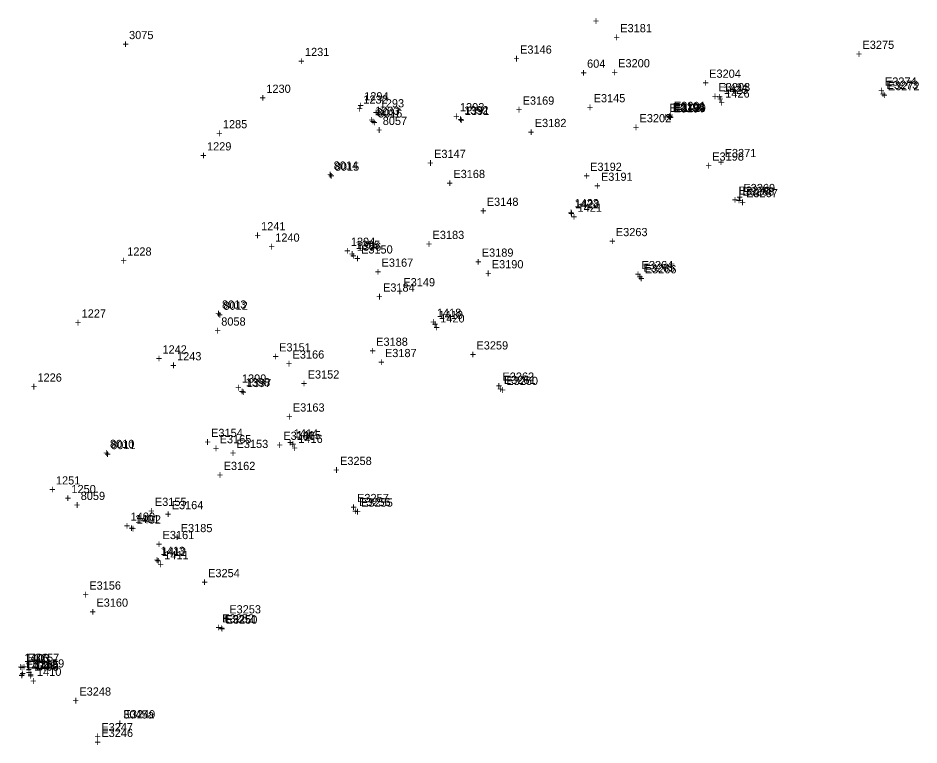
# Model space of a CAD drawing. Extents: x 1667192 to 1669644, y 336680 to 339991.
# Drawn here: x 1668014.4 to 1668289.1, y 339181.7 to 339403.5 of the extents above; entities that cross this region are included whole.
import ezdxf

# ---------------------------------------------------------------- set-up
doc = ezdxf.new("R2010")
doc.units = 0
for name, color, linetype in [('S_Control_Temp_Traverse', 7, 'Continuous'), ('S_Curb_Type_1', 7, 'Continuous'), ('S_Curb_Type_5', 7, 'Continuous'), ('S_Drainage_CB', 7, 'Continuous'), ('S_Drainage_Culvert_Top', 7, 'Continuous'), ('S_Drainage_Invert', 7, 'Continuous'), ('S_Drainage_Sump', 7, 'Continuous'), ('S_Fencing_Page', 7, 'Continuous'), ('S_Ground_Elevation', 7, 'Continuous'), ('S_Roadway_Edge_Pavement', 7, 'Continuous'), ('S_Roadway_Edge_TW', 7, 'Continuous'), ('S_Traffic_Sign_SinglePost', 7, 'Continuous'), ('S_Trees_TreeLine', 7, 'Continuous')]:
    doc.layers.add(name, color=color, linetype=linetype)

msp = doc.modelspace()

# ---------------------------------------------------------------- texts
at = {"layer": 'S_Control_Temp_Traverse'}
for s, p in [('604', (1668187.89, 339388.33)), ('604', (1668187.89, 339388.33)), ('604', (1668187.89, 339388.33)), ('604', (1668187.89, 339388.33)), ('604', (1668187.89, 339388.33)), ('604', (1668187.89, 339388.33)), ('604', (1668187.89, 339388.33)), ('604', (1668187.89, 339388.33)), ('604', (1668187.89, 339388.33)), ('+', (1668185.83, 339385.58)), ('+', (1668185.83, 339385.58)), ('+', (1668185.83, 339385.58)), ('+', (1668185.83, 339385.58)), ('+', (1668185.83, 339385.58)), ('+', (1668185.83, 339385.58)), ('+', (1668185.83, 339385.58)), ('+', (1668185.83, 339385.58)), ('+', (1668185.83, 339385.58))]:
    msp.add_text(s, height=2.5, dxfattribs=at).set_placement(p)
at = {"layer": 'S_Curb_Type_1'}
for s, p in [('1424', (1668229.43, 339381)), ('+', (1668227.37, 339378.25)), ('8017', (1668123.69, 339373.48)), ('1391', (1668150.63, 339373.9)), ('+', (1668121.63, 339370.73)), ('+', (1668148.57, 339371.15)), ('8014', (1668110.63, 339357.25)), ('+', (1668108.57, 339354.5)), ('1423', (1668184.06, 339345.77)), ('+', (1668182, 339343.02)), ('1396', (1668117.69, 339332.5)), ('+', (1668115.62, 339329.75)), ('8013', (1668076.56, 339314.85)), ('1418', (1668142.09, 339312.32)), ('+', (1668074.5, 339312.1)), ('+', (1668140.03, 339309.57)), ('1397', (1668084.14, 339290.91)), ('+', (1668082.08, 339288.16)), ('1414', (1668098.44, 339275.52)), ('8010', (1668042.4, 339272.32)), ('+', (1668096.38, 339272.77)), ('+', (1668040.34, 339269.57)), ('1402', (1668050.53, 339249.25)), ('+', (1668048.47, 339246.5)), ('1413', (1668057.84, 339239.68)), ('+', (1668055.77, 339236.93)), ('1404', (1668016.67, 339204.62)), ('1403', (1668016.68, 339206.91)), ('1405', (1668019.34, 339204.8)), ('+', (1668014.62, 339204.16)), ('+', (1668014.61, 339201.87)), ('+', (1668017.28, 339202.05))]:
    msp.add_text(s, height=2.5, dxfattribs=at).set_placement(p)
at = {"layer": 'S_Curb_Type_5'}
for s, p in [('E3272', (1668279.6, 339381.48)), ('+', (1668277.54, 339378.73)), ('E3267', (1668236.38, 339348.83)), ('+', (1668234.32, 339346.08)), ('E3266', (1668205.47, 339325.6)), ('+', (1668203.41, 339322.85)), ('E3260', (1668163.25, 339291.55)), ('+', (1668161.19, 339288.8)), ('E3255', (1668118.98, 339254.42)), ('+', (1668116.92, 339251.67)), ('E3250', (1668077.67, 339218.71)), ('+', (1668075.61, 339215.96)), ('3045a', (1668046.47, 339189.81)), ('E3249', (1668046.52, 339189.85)), ('+', (1668044.41, 339187.06)), ('+', (1668044.46, 339187.1))]:
    msp.add_text(s, height=2.5, dxfattribs=at).set_placement(p)
at = {"layer": 'S_Drainage_CB'}
for s, p in [('E3201', (1668214.36, 339375.43)), ('+', (1668212.3, 339372.68)), ('E3270', (1668234.09, 339349.59)), ('+', (1668232.03, 339346.84)), ('E3253', (1668078.78, 339221.86)), ('+', (1668076.72, 339219.11))]:
    msp.add_text(s, height=2.5, dxfattribs=at).set_placement(p)
at = {"layer": 'S_Drainage_Culvert_Top'}
for s, p in [('E3200', (1668197.37, 339388.45)), ('+', (1668195.31, 339385.7)), ('E3197', (1668214.21, 339374.68)), ('E3199', (1668214.43, 339374.79)), ('+', (1668212.15, 339371.93)), ('+', (1668212.36, 339372.04)), ('E3198', (1668226.05, 339359.99)), ('+', (1668223.99, 339357.24))]:
    msp.add_text(s, height=2.5, dxfattribs=at).set_placement(p)
at = {"layer": 'S_Drainage_Invert'}
for s, p in [('E3195', (1668214.17, 339375.02)), ('+', (1668212.11, 339372.27))]:
    msp.add_text(s, height=2.5, dxfattribs=at).set_placement(p)
at = {"layer": 'S_Drainage_Sump'}
for s, p in [('E3194', (1668214.05, 339375.08)), ('+', (1668211.99, 339372.33))]:
    msp.add_text(s, height=2.5, dxfattribs=at).set_placement(p)
at = {"layer": 'S_Fencing_Page'}
for s, p in [('3075', (1668048.22, 339397.06)), ('+', (1668046.16, 339394.31))]:
    msp.add_text(s, height=2.5, dxfattribs=at).set_placement(p)
at = {"layer": 'S_Ground_Elevation'}
for s, p in [('+', (1668189.66, 339401.4)), ('E3181', (1668198, 339399.15)), ('+', (1668195.94, 339396.4)), ('1231', (1668101.86, 339391.9)), ('E3146', (1668167.45, 339392.62)), ('+', (1668099.8, 339389.15)), ('+', (1668165.39, 339389.87)), ('E3204', (1668225.12, 339385.27)), ('1230', (1668090.08, 339380.67)), ('+', (1668223.06, 339382.52)), ('E3203', (1668227.95, 339381.17)), ('1294', (1668119.91, 339378.37)), ('E3145', (1668189.89, 339377.79)), ('+', (1668225.89, 339378.42)), ('+', (1668088.02, 339377.92)), ('+', (1668117.85, 339375.62)), ('1232', (1668119.64, 339377.37)), ('1293', (1668124.65, 339376.23)), ('E3169', (1668168.23, 339377.06)), ('+', (1668117.58, 339374.62)), ('+', (1668122.58, 339373.48)), ('1233', (1668123.26, 339373.94)), ('+', (1668166.17, 339374.31)), ('+', (1668187.83, 339375.04)), ('E3193', (1668212.97, 339374.84)), ('+', (1668121.2, 339371.19)), ('E3182', (1668171.92, 339370.23)), ('+', (1668210.91, 339372.09)), ('+', (1668169.86, 339367.48)), ('1229', (1668071.99, 339363.1)), ('+', (1668069.93, 339360.35)), ('E3147', (1668141.22, 339360.79)), ('+', (1668139.16, 339358.04)), ('E3192', (1668188.82, 339356.87)), ('E3168', (1668147.11, 339354.67)), ('+', (1668186.76, 339354.12)), ('E3191', (1668192.12, 339353.84)), ('+', (1668145.05, 339351.92)), ('+', (1668190.06, 339351.09)), ('E3148', (1668157.3, 339346.2)), ('+', (1668155.24, 339343.45)), ('1241', (1668088.48, 339338.73)), ('+', (1668086.42, 339335.98)), ('1240', (1668092.79, 339335.27)), ('E3183', (1668140.76, 339336.08)), ('1228', (1668047.65, 339331.02)), ('+', (1668090.73, 339332.52)), ('E3150', (1668118.95, 339331.65)), ('+', (1668138.7, 339333.33)), ('+', (1668116.89, 339328.9)), ('E3189', (1668155.77, 339330.68)), ('+', (1668045.58, 339328.27)), ('E3167', (1668125.21, 339327.62)), ('+', (1668153.71, 339327.93)), ('E3190', (1668158.82, 339327.13)), ('+', (1668123.15, 339324.87)), ('+', (1668156.76, 339324.38)), ('E3184', (1668125.66, 339320.02)), ('E3149', (1668131.86, 339321.65)), ('+', (1668129.8, 339318.9)), ('+', (1668123.6, 339317.27)), ('1227', (1668033.76, 339312.12)), ('+', (1668031.7, 339309.37)), ('1242', (1668058.4, 339301.15)), ('E3151', (1668093.98, 339301.78)), ('E3188', (1668123.57, 339303.5)), ('1243', (1668062.84, 339299.06)), ('+', (1668091.92, 339299.03)), ('E3166', (1668098.07, 339299.6)), ('+', (1668121.51, 339300.75)), ('E3187', (1668126.25, 339300.05)), ('+', (1668056.34, 339298.4)), ('+', (1668060.78, 339296.31)), ('+', (1668096.01, 339296.85)), ('+', (1668124.19, 339297.3)), ('1226', (1668020.28, 339292.57)), ('E3152', (1668102.67, 339293.52)), ('+', (1668100.61, 339290.77)), ('+', (1668018.22, 339289.82)), ('E3163', (1668098.17, 339283.44)), ('+', (1668096.11, 339280.69)), ('E3154', (1668073.24, 339275.68)), ('E3165', (1668075.84, 339273.77)), ('E3186', (1668095.25, 339274.79)), ('+', (1668071.18, 339272.93)), ('+', (1668073.78, 339271.02)), ('E3153', (1668080.99, 339272.32)), ('+', (1668093.19, 339272.04)), ('+', (1668078.93, 339269.57)), ('E3162', (1668077.06, 339265.61)), ('+', (1668075, 339262.86)), ('1251', (1668025.92, 339261.19)), ('+', (1668023.86, 339258.44)), ('1250', (1668030.64, 339258.55)), ('+', (1668028.58, 339255.8)), ('E3155', (1668056.09, 339254.65)), ('+', (1668054.03, 339251.9)), ('E3164', (1668061.21, 339253.66)), ('+', (1668059.15, 339250.91)), ('E3185', (1668063.97, 339246.65)), ('E3161', (1668058.43, 339244.53)), ('+', (1668061.91, 339243.9)), ('+', (1668056.37, 339241.78)), ('E3156', (1668036.09, 339229.12)), ('+', (1668034.03, 339226.37)), ('E3160', (1668038.25, 339223.9)), ('+', (1668036.19, 339221.15)), ('E3158', (1668016.83, 339205.09)), ('E3157', (1668017.25, 339207.08)), ('E3159', (1668018.77, 339205.35)), ('+', (1668014.77, 339202.34)), ('+', (1668015.19, 339204.33)), ('+', (1668016.71, 339202.6))]:
    msp.add_text(s, height=2.5, dxfattribs=at).set_placement(p)
at = {"layer": 'S_Roadway_Edge_Pavement'}
for s, p in [('E3273', (1668279.21, 339381.88)), ('1425', (1668229.57, 339380.35)), ('+', (1668277.14, 339379.13)), ('+', (1668227.51, 339377.6)), ('8016', (1668124.11, 339373.15)), ('1392', (1668150.38, 339374.11)), ('+', (1668122.04, 339370.4)), ('+', (1668148.32, 339371.36)), ('8015', (1668110.94, 339356.91)), ('+', (1668108.88, 339354.16)), ('E3268', (1668235.3, 339349.35)), ('1422', (1668184.22, 339345.43)), ('+', (1668233.24, 339346.6)), ('+', (1668182.16, 339342.68)), ('1395', (1668117.33, 339333.05)), ('+', (1668115.27, 339330.3)), ('E3265', (1668205.07, 339326.08)), ('+', (1668203.01, 339323.33)), ('8012', (1668076.97, 339314.48)), ('+', (1668074.91, 339311.73)), ('1419', (1668142.63, 339311.66)), ('+', (1668140.57, 339308.91)), ('1398', (1668083.79, 339291.12)), ('E3261', (1668162.53, 339291.85)), ('+', (1668081.73, 339288.37)), ('+', (1668160.46, 339289.1)), ('1415', (1668099.26, 339275.01)), ('8011', (1668042.74, 339271.97)), ('+', (1668097.2, 339272.26)), ('+', (1668040.68, 339269.22)), ('E3256', (1668118.32, 339254.59)), ('+', (1668116.26, 339251.84)), ('1401', (1668050.05, 339249.41)), ('+', (1668047.99, 339246.66)), ('1412', (1668058.17, 339239.42)), ('+', (1668056.11, 339236.67)), ('E3251', (1668077.53, 339218.9)), ('+', (1668075.47, 339216.15)), ('1406', (1668016.25, 339207.04)), ('+', (1668014.19, 339204.29)), ('1407', (1668016.59, 339204.48)), ('1408', (1668019.32, 339204.36)), ('+', (1668014.53, 339201.73)), ('+', (1668017.25, 339201.61)), ('E3246', (1668039.76, 339184.15)), ('+', (1668037.7, 339181.4))]:
    msp.add_text(s, height=2.5, dxfattribs=at).set_placement(p)
at = {"layer": 'S_Roadway_Edge_TW'}
for s, p in [('E3275', (1668271.87, 339394.08)), ('+', (1668269.81, 339391.33)), ('E3274', (1668278.71, 339382.87)), ('1426', (1668230.01, 339379.22)), ('+', (1668276.65, 339380.12)), ('1393', (1668149.13, 339375.05)), ('+', (1668227.95, 339376.47)), ('8057', (1668125.57, 339370.87)), ('+', (1668147.07, 339372.3)), ('+', (1668123.51, 339368.12)), ('E3271', (1668229.84, 339361.06)), ('+', (1668227.78, 339358.31)), ('E3269', (1668235.55, 339350.39)), ('+', (1668233.49, 339347.64)), ('1421', (1668184.98, 339344.4)), ('+', (1668182.92, 339341.65)), ('E3263', (1668196.66, 339336.95)), ('1394', (1668115.85, 339333.99)), ('+', (1668194.6, 339334.2)), ('+', (1668113.79, 339331.24)), ('E3264', (1668204.5, 339326.88)), ('+', (1668202.44, 339324.13)), ('8058', (1668076.33, 339309.66)), ('1420', (1668143.09, 339310.62)), ('+', (1668074.27, 339306.91)), ('+', (1668141.03, 339307.87)), ('E3259', (1668154.15, 339302.38)), ('+', (1668152.08, 339299.63)), ('E3262', (1668162.07, 339292.85)), ('1399', (1668082.65, 339292.27)), ('+', (1668080.59, 339289.52)), ('+', (1668160.01, 339290.1)), ('1416', (1668099.82, 339273.87)), ('+', (1668097.76, 339271.12)), ('E3258', (1668112.55, 339267.14)), ('+', (1668110.49, 339264.39)), ('8059', (1668033.47, 339256.46)), ('E3257', (1668117.75, 339255.82)), ('+', (1668031.41, 339253.71)), ('+', (1668115.69, 339253.07)), ('1400', (1668048.7, 339250.14)), ('+', (1668046.64, 339247.39)), ('1411', (1668058.95, 339238.37)), ('+', (1668056.89, 339235.62)), ('E3254', (1668072.32, 339232.91)), ('+', (1668070.26, 339230.16)), ('E3252', (1668076.64, 339219.1)), ('+', (1668074.58, 339216.36)), ('1410', (1668020.14, 339202.8)), ('+', (1668018.08, 339200.05)), ('E3248', (1668033.06, 339196.79)), ('+', (1668031, 339194.04)), ('E3247', (1668039.75, 339185.91)), ('+', (1668037.69, 339183.16))]:
    msp.add_text(s, height=2.5, dxfattribs=at).set_placement(p)
at = {"layer": 'S_Traffic_Sign_SinglePost'}
for s, p in [('E3202', (1668203.88, 339371.69)), ('+', (1668201.82, 339368.94))]:
    msp.add_text(s, height=2.5, dxfattribs=at).set_placement(p)
at = {"layer": 'S_Trees_TreeLine'}
for s, p in [('1285', (1668076.82, 339369.86)), ('+', (1668074.76, 339367.11))]:
    msp.add_text(s, height=2.5, dxfattribs=at).set_placement(p)

doc.saveas('drawing.dxf')
